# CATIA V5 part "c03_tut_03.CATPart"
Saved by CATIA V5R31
Part number: c03tut3
Bounding box of the stored display mesh (mm): x 0 to 0, y -100 to 100, z 0 to 90
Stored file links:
  D:\PROJECTS\Project 2021\US EDITION\CATIA V5 6R 2021\Resources\Tutorial Files\c03_catia_v5_6r2021_tut\c03_tut_03.CATPart
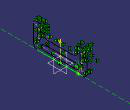
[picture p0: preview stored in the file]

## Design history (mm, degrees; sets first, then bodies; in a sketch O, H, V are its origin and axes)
Body1 (main body)
  Sketch1 on yz-plane, origin (0, 0, 0), H (0, 1, 0), V (0, 0, 1)
    line L1 (0, 0) -> (85, 0)
    line L2 (100, 15) -> (100, 80)
    line L3 (90, 90) -> (70, 90)
    line L4 (60, 80) -> (60, 60)
    line L5 (50, 50) -> (0, 50)
    point P1 (0, 50)
    arc A1 centre (85, 15) radius 15 from (85, 0) to (100, 15) ccw
    point P2 (85, 0)
    point P3 (100, 15)
    arc A2 centre (90, 80) radius 10 from (100, 80) to (90, 90) ccw
    point P5 (100, 80)
    point P6 (90, 90)
    arc A3 centre (70, 80) radius 10 from (70, 90) to (60, 80) ccw
    point P8 (70, 90)
    point P9 (60, 80)
    arc A4 centre (50, 60) radius 10 from (60, 60) to (50, 50) cw
    point P11 (60, 60)
    point P12 (50, 50)
    construction line L6 (80, 40) -> (80, 70)
    line L7 (75, 40) -> (75, 70)
    line L8 (85, 70) -> (85, 40)
    arc A5 centre (80, 70) radius 5 from (75, 70) to (85, 70) cw
    arc A6 centre (80, 40) radius 5 from (85, 40) to (75, 40) cw
    point P16 (75, 40)
    point P17 (75, 70)
    point P18 (85, 70)
    point P19 (85, 40)
    point P20 (0, 0)
    construction line L9 through (0, 0) direction (-1, 0)
    point P21 (0, 50)
    point P22 (-85, 0)
    point P23 (-100, 15)
    point P25 (-100, 80)
    point P26 (-90, 90)
    point P28 (-70, 90)
    point P29 (-60, 80)
    point P31 (-60, 60)
    point P32 (-50, 50)
    construction line L10 (-80, 40) -> (-80, 70)
    point P36 (-75, 40)
    point P37 (-75, 70)
    point P38 (-85, 70)
    point P39 (-85, 40)
    line L11 (-100, 15) -> (-100, 80)
    line L12 (-90, 90) -> (-70, 90)
    line L13 (-60, 80) -> (-60, 60)
    line L14 (-50, 50) -> (0, 50)
    arc A7 centre (-85, 15) radius 15 from (-85, 0) to (-100, 15) cw
    arc A8 centre (-90, 80) radius 10 from (-100, 80) to (-90, 90) cw
    arc A9 centre (-70, 80) radius 10 from (-70, 90) to (-60, 80) cw
    arc A10 centre (-50, 60) radius 10 from (-60, 60) to (-50, 50) ccw
    line L15 (-75, 40) -> (-75, 70)
    line L16 (-85, 70) -> (-85, 40)
    arc A11 centre (-80, 70) radius 5 from (-75, 70) to (-85, 70) ccw
    arc A12 centre (-80, 40) radius 5 from (-85, 40) to (-75, 40) ccw
    line L17 (0, 0) -> (-85, 0)
    construction line L18 (60, 20) -> (-60, 20)
    point P40 (-60, 20)
    line L19 (60, 10) -> (-60, 10)
    line L20 (-60, 30) -> (60, 30)
    arc A13 centre (-60, 20) radius 10 from (-60, 10) to (-60, 30) cw
    arc A14 centre (60, 20) radius 10 from (60, 30) to (60, 10) cw
    radius A1 = 15
    radius A2 = 10
    radius A3 = 10
    radius A4 = 10
    distance L6 L7 = 5
    distance L18 L19 = 10
    horizontal: L1 H, L3 H, L5 H, L18 H
    vertical: L2 V, L4 V, L6 V
    tangency: A1 L1, A1 L2, A2 L2, A2 L3, A3 L3, A3 L4, A4 L4, A4 L5, A5 L7, A6 L7, A5 L8, A6 L8, A13 L19, A14 L19, A13 L20, A14 L20
    symmetry: O P20 V, H L9 V, P1 P21 V, P2 P22 V, P3 P23 V, P5 P25 V, P6 P26 V, P8 P28 V, P9 P29 V, P11 P31 V, P12 P32 V, L6 L10 V, P16 P36 V, P17 P37 V, P18 P38 V, P19 P39 V, L2 L11 V, L3 L12 V, L4 L13 V, L5 L14 V, A1 A7 V, A2 A8 V, A3 A9 V, A4 A10 V, L7 L15 V, L8 L16 V, A5 A11 V, A6 A12 V, L1 L17 V
    coincidence: P40 L13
